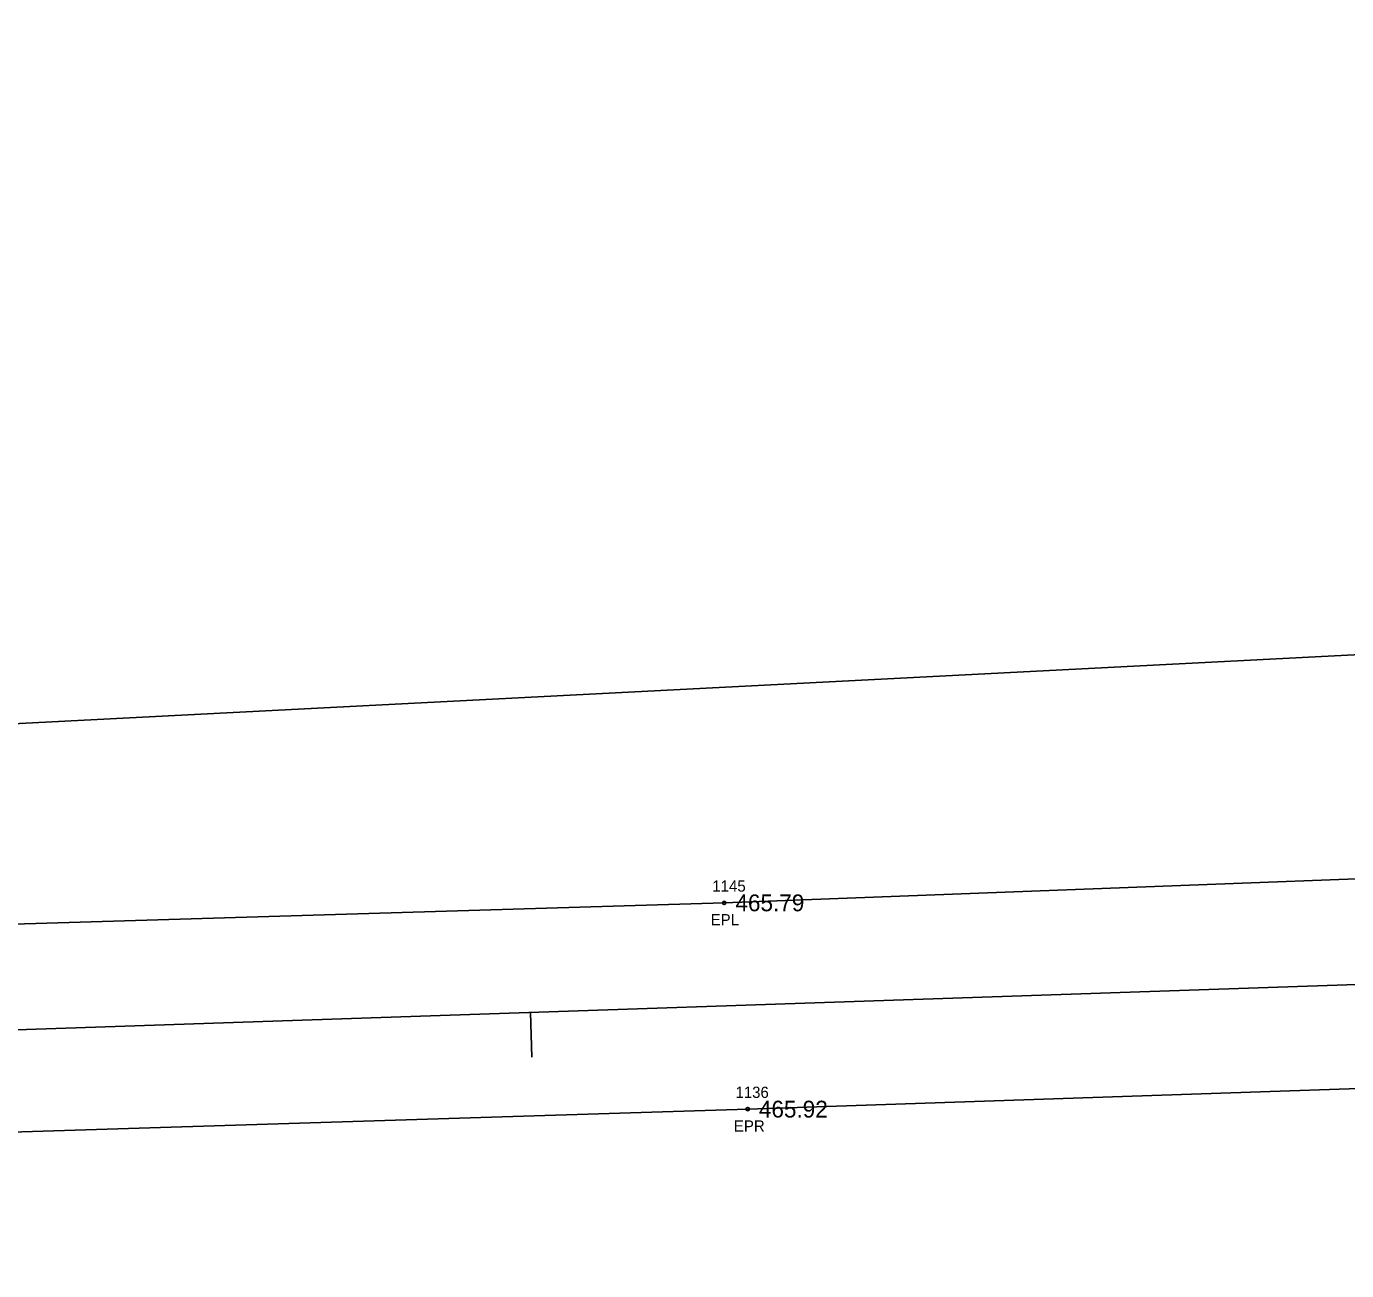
# Model space of a CAD drawing. Extents: x 1784103 to 1787401, y 770251 to 771298.
# Drawn here: x 1785914.9 to 1786032.5, y 770836.9 to 770947.8 of the extents above; entities that cross this region are included whole.
import ezdxf

# ---------------------------------------------------------------- set-up
doc = ezdxf.new("R2010")
doc.units = 0
for name, color, linetype in [('RD_EX_Road', 7, 'Continuous'), ('RD_EX_Road_txCode', 7, 'Continuous'), ('RD_EX_TX_Road_ELEV', 7, 'Continuous'), ('RD_EX_VEG', 7, 'Continuous'), ('RD_HC_Cl', 7, 'Continuous'), ('RD_HC_Data_Tic', 7, 'Continuous'), ('RD_SMD_Locator', 7, 'Continuous')]:
    doc.layers.add(name, color=color, linetype=linetype)

msp = doc.modelspace()

# ---------------------------------------------------------------- linework, layer by layer
at = {"layer": 'RD_EX_Road'}
for points in [[(1785824.57, 770864.86), (1785879.1, 770866.73), (1785977.08, 770869.67), (1786078.78, 770873.52), (1786179.09, 770876.83), (1786278.08, 770880.28), (1786358.72, 770883.31), (1786381.38, 770883.94), (1786478.25, 770886.75), (1786578.04, 770889.63)], [(1785825.31, 770845.6), (1785879.29, 770848.18), (1785979.17, 770851.29), (1786079.29, 770854.66), (1786178.79, 770858.1), (1786233.56, 770860.16), (1786246.2, 770860.52), (1786278.61, 770861.3), (1786379.15, 770864.94), (1786479.01, 770868.57), (1786578.78, 770871.53)]]:
    msp.add_lwpolyline(points, dxfattribs=at)
at = {"layer": 'RD_EX_VEG'}
msp.add_lwpolyline([(1785221.61, 770869.17), (1785226.44, 770862.44), (1785230.83, 770863.64), (1785281.61, 770865.88), (1785330.18, 770866.95), (1785378.64, 770865.28), (1785481.03, 770871.22), (1785579.9, 770882.43), (1785678.49, 770873.66), (1785753.25, 770880.69), (1785777.57, 770887.66), (1785796.72, 770894.6), (1785878.49, 770883.8), (1786077.63, 770894.05), (1786177.75, 770898.7), (1786232.19, 770912.93), (1786276.99, 770915.77), (1786313.89, 770919.94), (1786357.9, 770947.77)], dxfattribs=at)
at = {"layer": 'RD_HC_Cl'}
msp.add_line((1787025.56, 770895.93), (1785279.14, 770836.9), dxfattribs=at)
at = {"layer": 'RD_HC_Data_Tic'}
msp.add_line((1785959.81, 770859.91), (1785959.95, 770855.91), dxfattribs=at)
at = {"layer": 'RD_SMD_Locator'}
for centre in [(1785977.08, 770869.67), (1785979.17, 770851.29)]:
    msp.add_circle(centre, 0.15, dxfattribs=at)

# ---------------------------------------------------------------- texts
at = {"layer": 'RD_EX_Road_txCode'}
for s, p in [('1145', (1785976.02, 770870.67)), ('EPL', (1785975.87, 770867.67)), ('1136', (1785978.08, 770852.29)), ('EPR', (1785977.94, 770849.29))]:
    msp.add_text(s, height=1, dxfattribs=at).set_placement(p)
at = {"layer": 'RD_EX_TX_Road_ELEV'}
for s, p in [('465.79', (1785978.08, 770868.92)), ('465.92', (1785980.17, 770850.54))]:
    msp.add_text(s, height=1.5, dxfattribs=at).set_placement(p)

doc.saveas('drawing.dxf')
